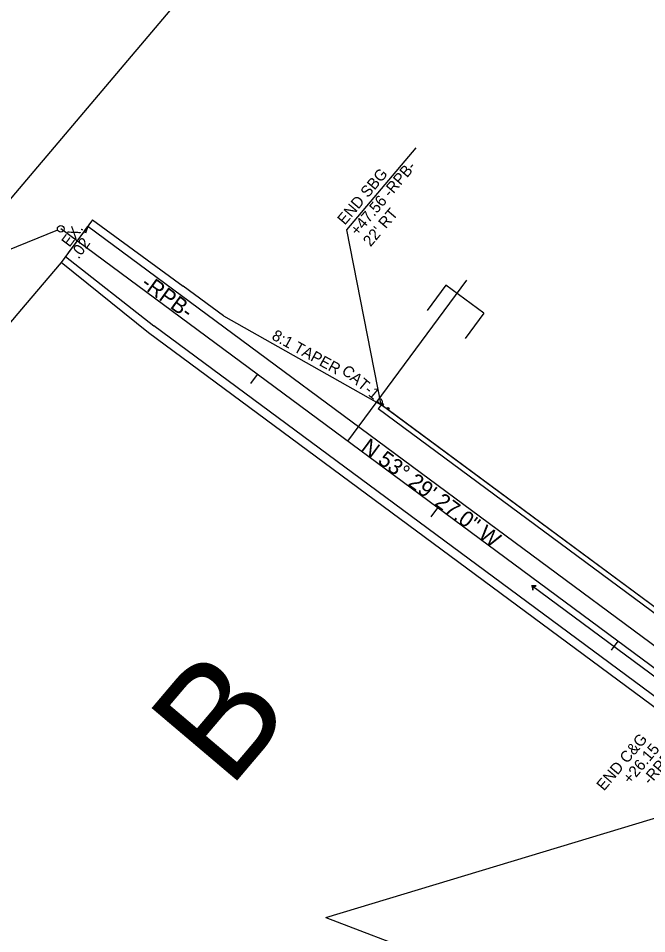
# Model space of a CAD drawing. Extents: x 1761082 to 1764358, y 421907 to 425434.
# Drawn here: x 1762337.6 to 1762617.9, y 423617.8 to 424026 of the extents above; entities that cross this region are included whole.
import ezdxf

# ---------------------------------------------------------------- set-up
doc = ezdxf.new("R2010")
doc.units = 0
for name, color, linetype in [('MARK DUAL LEFT TURN ARROWS CELL', 7, 'Continuous'), ('MARK HOOKS CENTER LEFT TURN ARROW CELL', 7, 'Continuous'), ('MARK HOOKS CENTER STRAIGHT LEFT TURN ARROW CELL', 7, 'Continuous'), ('MARK HOOKS STRAIGHT RIGHT TURN ARROW CELL', 7, 'Continuous'), ('MARK LEFT TURN ARROW CELL', 7, 'Continuous'), ('MARK STRAIGHT RIGHT ARROW CELL', 7, 'Continuous'), ('MARK UTURN ARROW CELL', 7, 'Continuous'), ('Prop Conc Shoulder Berm Gutter', 7, 'Continuous'), ('Prop Mkg 3ft Min Skp 3ft Wide White', 7, 'Continuous'), ('Prop Mkg 3ft Min Skp 9ft Wide White', 7, 'Continuous'), ('Prop Mkg Min Skp 6ft Yellow', 7, 'Continuous'), ('Prop Mkg Skp Wht', 7, 'Continuous'), ('Prop Mkg Solid White Multiple Diagonals V8i', 7, 'Continuous'), ('Prop Mkg Solid White Stop Bar', 7, 'Continuous'), ('Prop Mkg Solid Yel Skip LT', 7, 'Continuous'), ('Prop Mkg Solid Yel Skip RT', 7, 'Continuous'), ('Prop Mkg Yld Lin', 7, 'Continuous'), ('Prop Mkr Yel 80ft Spc', 7, 'Continuous'), ('Scratch_Level_1', 7, 'Continuous'), ('Scratch_Level_5', 7, 'Continuous')]:
    doc.layers.add(name, color=color, linetype=linetype)

msp = doc.modelspace()

# ---------------------------------------------------------------- linework, layer by layer
at = {"layer": 'MARK DUAL LEFT TURN ARROWS CELL'}
msp.add_line((1762537.45, 423909.18), (1762484.38, 423837.49), dxfattribs=at)
at = {"layer": 'MARK HOOKS CENTER STRAIGHT LEFT TURN ARROW CELL'}
for p, q in [((1762363.82, 423926.73), (1762360.84, 423922.72)), ((1762444.19, 423867.24), (1762441.22, 423863.22)), ((1762524.57, 423807.74), (1762521.6, 423803.72)), ((1762604.95, 423748.25), (1762601.97, 423744.23))]:
    msp.add_line(p, q, dxfattribs=at)
at = {"layer": 'MARK LEFT TURN ARROW CELL'}
for p, q in [((1762528.35, 423906.97), (1762520.02, 423895.72)), ((1762545.23, 423894.48), (1762528.35, 423906.97)), ((1762545.23, 423894.48), (1762536.9, 423883.22))]:
    msp.add_line(p, q, dxfattribs=at)
at = {"layer": 'MARK STRAIGHT RIGHT ARROW CELL'}
msp.add_line((1762685.32, 423688.75), (1762356.55, 423932.12), dxfattribs=at)
at = {"layer": 'MARK UTURN ARROW CELL'}
for points in [[(1762355.16, 423931.55), (1762291.29, 423905.65), (1762208.3, 423807.69)], [(1762356.7, 423917.11), (1762340.72, 423898.25), (1762255.29, 423797.41)]]:
    msp.add_lwpolyline(points, dxfattribs=at)
msp.add_circle((1762356.55, 423932.12), 1.5, dxfattribs=at)
at = {"layer": 'Prop Conc Shoulder Berm Gutter'}
for p, q in [((1762499.43, 423853.72), (1762498.05, 423851.85)), ((1762680.28, 423719.85), (1762499.43, 423853.72))]:
    msp.add_line(p, q, dxfattribs=at)
at = {"layer": 'Prop Mkg 3ft Min Skp 3ft Wide White'}
msp.add_line((1762685.32, 423688.75), (1762356.55, 423932.12), dxfattribs=at)
at = {"layer": 'Prop Mkg 3ft Min Skp 9ft Wide White'}
msp.add_line((1762680.28, 423719.85), (1762502.5, 423851.46), dxfattribs=at)
at = {"layer": 'Prop Mkg Skp Wht'}
for p, q in [((1762370.77, 423936.13), (1762356.7, 423917.11)), ((1762671.95, 423708.6), (1762368.58, 423933.16)), ((1762358.73, 423919.86), (1762398.06, 423888.95)), ((1762669.26, 423688.2), (1762398.06, 423888.95))]:
    msp.add_line(p, q, dxfattribs=at)
at = {"layer": 'Prop Mkg Solid White Multiple Diagonals V8i'}
for p, q in [((1761203.63, 422611.03), (1763595.27, 425434.16)), ((1762474.81, 423624.99), (1762733.71, 423703.41)), ((1762474.81, 423624.99), (1762680.43, 423546.86))]:
    msp.add_line(p, q, dxfattribs=at)
at = {"layer": 'Prop Mkg Solid White Stop Bar'}
for p, q in [((1762370.77, 423936.13), (1762411.15, 423906.63)), ((1762395.68, 423885.73), (1762356.7, 423917.11)), ((1762429.18, 423893.28), (1762411.15, 423906.63)), ((1762429.18, 423893.28), (1762499.43, 423853.72)), ((1762655.98, 423693.06), (1762395.68, 423885.73)), ((1762678.9, 423717.98), (1762498.05, 423851.85))]:
    msp.add_line(p, q, dxfattribs=at)
at = {"layer": 'Prop Mkg Solid Yel Skip RT'}
msp.add_lwpolyline([(1762499.43, 423853.72), (1762484.09, 423931.77), (1762515.02, 423968.28)], dxfattribs=at)
at = {"layer": 'Prop Mkg Yld Lin'}
for p, q in [((1762499.85, 423855.39), (1762499.85, 423854.29)), ((1762499.65, 423853.56), (1762498.27, 423854.59)), ((1762499.43, 423853.72), (1762499.91, 423854.37)), ((1762499.43, 423853.72), (1762500.48, 423853.95)), ((1762500, 423853.31), (1762499.43, 423853.72)), ((1762499.54, 423853.64), (1762499.65, 423853.56)), ((1762502.5, 423851.46), (1762499.65, 423853.56)), ((1762499.91, 423854.37), (1762500.48, 423853.95)), ((1762500, 423853.31), (1762499.91, 423854.37)), ((1762499.96, 423853.84), (1762501.24, 423852.38)), ((1762500.48, 423853.95), (1762500, 423853.31)), ((1762501.93, 423851.87), (1762502.41, 423852.52)), ((1762501.93, 423851.87), (1762502.98, 423852.1)), ((1762502.5, 423851.46), (1762501.93, 423851.87)), ((1762502.41, 423852.52), (1762502.98, 423852.1)), ((1762502.5, 423851.46), (1762502.41, 423852.52)), ((1762502.98, 423852.1), (1762502.5, 423851.46))]:
    msp.add_line(p, q, dxfattribs=at)
msp.add_ellipse((1762498.86, 423855.38), major_axis=(-0.591, -0.798), ratio=0.995379, start_param=2.210226, end_param=6.283185, dxfattribs=at)
at = {"layer": 'Prop Mkr Yel 80ft Spc'}
msp.add_line((1762661.6, 423702.58), (1762566.59, 423772.91), dxfattribs=at)
msp.add_lwpolyline([(1762566.59, 423772.91), (1762567.14, 423770.99), (1762567.39, 423772.32), (1762568.58, 423772.95)], close=True, dxfattribs=at)
msp.add_circle((1762566.59, 423772.91), 0.0417, dxfattribs=at)
at = {"layer": 'Scratch_Level_1'}
msp.add_line((1762670.21, 423696.21), (1762566.59, 423772.91), dxfattribs=at)
msp.add_lwpolyline([(1762566.59, 423772.91), (1762567.14, 423770.99), (1762567.39, 423772.32), (1762568.58, 423772.95)], close=True, dxfattribs=at)
msp.add_circle((1762566.59, 423772.91), 0.0417, dxfattribs=at)
at = {"layer": 'Scratch_Level_5'}
msp.add_line((1762368.58, 423933.16), (1762359.78, 423921.27), dxfattribs=at)
msp.add_lwpolyline([(1762368.58, 423933.16), (1762367.6, 423930.16), (1762367.2, 423931.31)], close=True, dxfattribs=at)

# ---------------------------------------------------------------- texts
at = {"layer": 'MARK HOOKS CENTER LEFT TURN ARROW CELL'}
msp.add_text('N 53%%d 29\' 27.0" W', height=7, rotation=323.4908, dxfattribs=at).set_placement((1762490.01, 423833.58))
at = {"layer": 'MARK HOOKS STRAIGHT RIGHT TURN ARROW CELL'}
msp.add_text('-RPB-', height=7, rotation=323.9176, dxfattribs=at).set_placement((1762391.89, 423906.62))
at = {"layer": 'Prop Mkg Min Skp 6ft Yellow'}
for s, p in [('EX.', (1762360.46, 423923.66)), ('.02', (1762364.51, 423918.38))]:
    msp.add_text(s, height=5, rotation=53.4908, dxfattribs=at).set_placement(p)
at = {"layer": 'Prop Mkg Solid Yel Skip LT'}
for s, height, rotation, p in [('END SBG', 5, 49.7301, (1762483.24, 423933.53)), ('+47.56 -RPB-', 5, 49.7301, (1762488.97, 423928.69)), ("22' RT", 5, 49.7301, (1762494.69, 423923.84)), ('8:1 TAPER', 5, 331.2209, (1762450.27, 423883.09)), ('B', 50, 49.7301, (1762431.68, 423681.92)), ('END C&G', 5, 49.7301, (1762598.81, 423681.2)), ('+26.15', 5, 49.7301, (1762610.55, 423684.23)), ('-RPB-', 5, 49.7301, (1762619.43, 423683.88))]:
    msp.add_text(s, height=height, rotation=rotation, dxfattribs=at).set_placement(p)
at = {"layer": 'Prop Mkg Yld Lin'}
msp.add_text('CAT-1', height=5, rotation=319.9656, dxfattribs=at).set_placement((1762481.41, 423868.11))

doc.saveas('drawing.dxf')
